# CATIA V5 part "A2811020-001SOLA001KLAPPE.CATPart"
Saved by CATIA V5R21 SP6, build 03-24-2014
Part number: A2811020-001SOLA001KLAPPE
Revision: --A
Definition: A2811020-001SOLA001.KLAPPE
Source: made
Description: START_SOLV5_EF2000______
Property "PTC_WM_NAME": "A2811020-001SOLA001.KLAPPE"
Property "PTC_WM_NUMBER": "A2811020-001SOLA001KLAPPE"
Property "PTC_WM_REVISION": "--A"
Property "PTC_WM_INIT_REV": "01"
Bounding box of the stored display mesh (mm): x 0 to 10, y -14.308 to 13.233, z 0 to 114.223
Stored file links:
  J:\Transfer\Fueller Werkstudent\Stellungen\A2811020-001SOLA001KLAPPE.CATPart
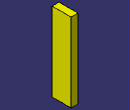
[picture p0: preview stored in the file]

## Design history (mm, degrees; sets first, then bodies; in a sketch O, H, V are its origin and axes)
AxisSystem1: origin (0, 0, 0), X (1, 0, 0), Y (0, 1, 0), Z (0, 0, 1)
Body1 (main body)
  Body2 "Positive"
    Sketch1 on yz-plane, origin (0, 0, 0), H (0, 1, 0), V (0, 0, 1)
      point P1 (-14.3076, 0)
      line L1 (-14.3076, 0) -> (13.2332, 0)
      line L2 (13.2332, 0) -> (13.2332, 114.2228)
      line L3 (13.2332, 114.2228) -> (-14.3076, 114.2228)
      line L4 (-14.3076, 114.2228) -> (-14.3076, 0)
      coincidence: P1 H
      horizontal: L1 H, L3 H
      vertical: L2 V, L4 V
    Pad1: profile Sketch1, direction (1, 0, 0), length 10
  Assemble1: tool Body2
